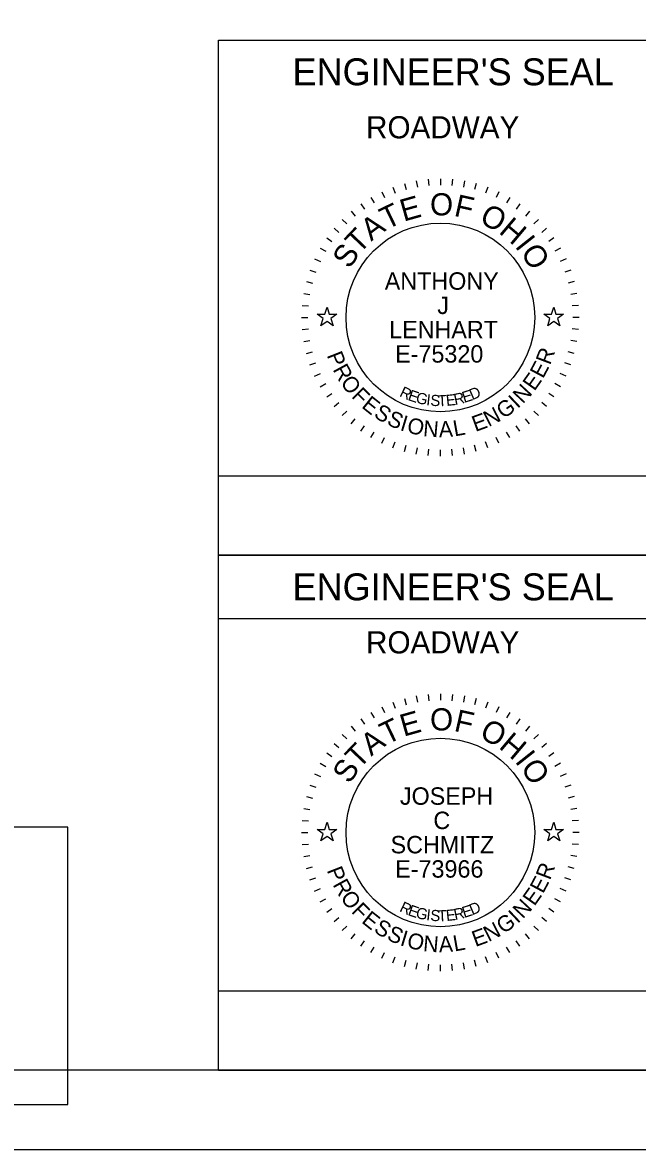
# Model space of a CAD drawing. Extents: x 208586767.6 to 208586821.4, y -134301046.9 to -134301022.9.
# Drawn here: x 208586783.14 to 208586787.02, y -134301044.94 to -134301037.83 of the extents above; entities that cross this region are included whole.
import ezdxf

# ---------------------------------------------------------------- set-up
doc = ezdxf.new("R2010")
doc.units = 0
for name, color, linetype in [('Default', 7, 'Continuous'), ('NO_PLOT', 7, 'Continuous'), ('SH_Border', 7, 'Continuous'), ('SH_Cut_Line', 7, 'Continuous'), ('SH_Data', 7, 'Continuous')]:
    doc.layers.add(name, color=color, linetype=linetype)

msp = doc.modelspace()

# ---------------------------------------------------------------- linework, layer by layer
at = {"layer": 'Default'}
for points in [[(208586785.0019, -134301039.6708), (208586785.0488, -134301039.6708), (208586785.0633, -134301039.6262), (208586785.0778, -134301039.6708), (208586785.1246, -134301039.6708), (208586785.0867, -134301039.6983), (208586785.1012, -134301039.7429), (208586785.0633, -134301039.7154), (208586785.0253, -134301039.7429), (208586785.0398, -134301039.6983)], [(208586786.4319, -134301039.6708), (208586786.4788, -134301039.6708), (208586786.4933, -134301039.6262), (208586786.5078, -134301039.6708), (208586786.5546, -134301039.6708), (208586786.5167, -134301039.6983), (208586786.5312, -134301039.7429), (208586786.4933, -134301039.7154), (208586786.4553, -134301039.7429), (208586786.4698, -134301039.6983)], [(208586785.0019, -134301042.9208), (208586785.0488, -134301042.9208), (208586785.0633, -134301042.8762), (208586785.0778, -134301042.9208), (208586785.1246, -134301042.9208), (208586785.0867, -134301042.9483), (208586785.1012, -134301042.9929), (208586785.0633, -134301042.9654), (208586785.0253, -134301042.9929), (208586785.0398, -134301042.9483)], [(208586786.4319, -134301042.9208), (208586786.4788, -134301042.9208), (208586786.4933, -134301042.8762), (208586786.5078, -134301042.9208), (208586786.5546, -134301042.9208), (208586786.5167, -134301042.9483), (208586786.5312, -134301042.9929), (208586786.4933, -134301042.9654), (208586786.4553, -134301042.9929), (208586786.4698, -134301042.9483)]]:
    msp.add_lwpolyline(points, close=True, dxfattribs=at)
at = {"layer": 'NO_PLOT'}
msp.add_lwpolyline([(208586777.4283, -134301044.6568), (208586783.4283, -134301044.6568), (208586783.4283, -134301042.9068), (208586777.4283, -134301042.9068)], close=True, dxfattribs=at)
at = {"layer": 'SH_Border'}
msp.add_lwpolyline([(208586777.4283, -134301023.4407), (208586809.4283, -134301023.4407), (208586809.4283, -134301044.4407), (208586777.4283, -134301044.4407)], close=True, dxfattribs=at)
at = {"layer": 'SH_Cut_Line'}
msp.add_lwpolyline([(208586775.9283, -134301044.9407), (208586809.9283, -134301044.9407), (208586809.9283, -134301022.9407), (208586775.9283, -134301022.9407)], close=True, dxfattribs=at)
at = {"layer": 'SH_Data'}
for p, q in [((208586784.3783, -134301041.1907), (208586784.3783, -134301037.9407)), ((208586784.3783, -134301037.9407), (208586787.1783, -134301037.9407)), ((208586785.5518, -134301038.8455), (208586785.5621, -134301038.8842)), ((208586785.6263, -134301038.829), (208586785.6333, -134301038.8684)), ((208586785.702, -134301038.819), (208586785.7055, -134301038.8589)), ((208586785.7783, -134301038.8157), (208586785.7783, -134301038.8557)), ((208586785.8545, -134301038.819), (208586785.851, -134301038.8589)), ((208586785.9302, -134301038.829), (208586785.9233, -134301038.8684)), ((208586786.0047, -134301038.8455), (208586785.9944, -134301038.8842)), ((208586785.4085, -134301038.8977), (208586785.4254, -134301038.934)), ((208586785.479, -134301038.8685), (208586785.4927, -134301038.9061)), ((208586786.0775, -134301038.8685), (208586786.0638, -134301038.9061)), ((208586786.1481, -134301038.8977), (208586786.1311, -134301038.934)), ((208586785.2764, -134301038.974), (208586785.2993, -134301039.0067)), ((208586785.3408, -134301038.9329), (208586785.3608, -134301038.9676)), ((208586786.2158, -134301038.9329), (208586786.1958, -134301038.9676)), ((208586786.2801, -134301038.974), (208586786.2572, -134301039.0067)), ((208586785.2158, -134301039.0204), (208586785.2415, -134301039.0511)), ((208586786.3407, -134301039.0204), (208586786.315, -134301039.0511)), ((208586785.108, -134301039.1283), (208586785.1386, -134301039.154)), ((208586785.1595, -134301039.072), (208586785.1878, -134301039.1003)), ((208586786.397, -134301039.072), (208586786.3687, -134301039.1003)), ((208586786.4486, -134301039.1283), (208586786.4179, -134301039.154)), ((208586785.0615, -134301039.1888), (208586785.0943, -134301039.2118)), ((208586786.495, -134301039.1888), (208586786.4623, -134301039.2118)), ((208586785.0205, -134301039.2532), (208586785.0551, -134301039.2732)), ((208586786.536, -134301039.2532), (208586786.5014, -134301039.2732)), ((208586784.9852, -134301039.3209), (208586785.0215, -134301039.3378)), ((208586786.5713, -134301039.3209), (208586786.535, -134301039.3378)), ((208586784.956, -134301039.3915), (208586784.9936, -134301039.4051)), ((208586786.6005, -134301039.3915), (208586786.5629, -134301039.4051)), ((208586784.9331, -134301039.4643), (208586784.9717, -134301039.4746)), ((208586786.6234, -134301039.4643), (208586786.5848, -134301039.4746)), ((208586784.9166, -134301039.5388), (208586784.9559, -134301039.5457)), ((208586786.64, -134301039.5388), (208586786.6006, -134301039.5457)), ((208586784.9066, -134301039.6145), (208586784.9464, -134301039.6179)), ((208586786.6499, -134301039.6145), (208586786.6101, -134301039.6179)), ((208586784.9033, -134301039.6907), (208586784.9433, -134301039.6907)), ((208586786.6533, -134301039.6907), (208586786.6133, -134301039.6907)), ((208586784.9066, -134301039.767), (208586784.9464, -134301039.7635)), ((208586786.6499, -134301039.767), (208586786.6101, -134301039.7635)), ((208586784.9166, -134301039.8427), (208586784.9559, -134301039.8357)), ((208586786.64, -134301039.8427), (208586786.6006, -134301039.8357)), ((208586784.9331, -134301039.9172), (208586784.9717, -134301039.9068)), ((208586786.6234, -134301039.9172), (208586786.5848, -134301039.9068)), ((208586784.956, -134301039.99), (208586784.9936, -134301039.9763)), ((208586786.6005, -134301039.99), (208586786.5629, -134301039.9763)), ((208586784.9852, -134301040.0605), (208586785.0215, -134301040.0436)), ((208586786.5713, -134301040.0605), (208586786.535, -134301040.0436)), ((208586785.0205, -134301040.1282), (208586785.0551, -134301040.1082)), ((208586786.536, -134301040.1282), (208586786.5014, -134301040.1082)), ((208586785.0615, -134301040.1926), (208586785.0943, -134301040.1697)), ((208586786.495, -134301040.1926), (208586786.4623, -134301040.1697)), ((208586785.108, -134301040.2532), (208586785.1386, -134301040.2274)), ((208586786.4486, -134301040.2532), (208586786.4179, -134301040.2274)), ((208586785.1595, -134301040.3094), (208586785.1878, -134301040.2812)), ((208586785.2158, -134301040.361), (208586785.2415, -134301040.3304)), ((208586786.3407, -134301040.361), (208586786.315, -134301040.3304)), ((208586786.397, -134301040.3094), (208586786.3687, -134301040.2812)), ((208586785.2764, -134301040.4075), (208586785.2993, -134301040.3747)), ((208586785.3408, -134301040.4485), (208586785.3608, -134301040.4139)), ((208586786.2158, -134301040.4485), (208586786.1958, -134301040.4139)), ((208586786.2801, -134301040.4075), (208586786.2572, -134301040.3747)), ((208586785.4085, -134301040.4837), (208586785.4254, -134301040.4475)), ((208586785.479, -134301040.513), (208586785.4927, -134301040.4754)), ((208586786.0775, -134301040.513), (208586786.0638, -134301040.4754)), ((208586786.1481, -134301040.4837), (208586786.1311, -134301040.4475)), ((208586785.5518, -134301040.5359), (208586785.5621, -134301040.4973)), ((208586785.6263, -134301040.5524), (208586785.6333, -134301040.513)), ((208586785.702, -134301040.5624), (208586785.7055, -134301040.5225)), ((208586785.7783, -134301040.5657), (208586785.7783, -134301040.5257)), ((208586785.8545, -134301040.5624), (208586785.851, -134301040.5225)), ((208586785.9302, -134301040.5524), (208586785.9233, -134301040.513)), ((208586786.0047, -134301040.5359), (208586785.9944, -134301040.4973)), ((208586784.3783, -134301044.4407), (208586784.3783, -134301041.1907)), ((208586784.3783, -134301041.1907), (208586787.1783, -134301041.1907)), ((208586784.3783, -134301041.1907), (208586787.1783, -134301041.1907)), ((208586784.3783, -134301044.4407), (208586784.3783, -134301041.1907)), ((208586784.3783, -134301041.1907), (208586787.1783, -134301041.1907)), ((208586784.3783, -134301041.5907), (208586787.1783, -134301041.5907)), ((208586785.479, -134301042.1185), (208586785.4927, -134301042.1561)), ((208586785.5518, -134301042.0955), (208586785.5621, -134301042.1342)), ((208586785.6263, -134301042.079), (208586785.6333, -134301042.1184)), ((208586785.702, -134301042.069), (208586785.7055, -134301042.1089)), ((208586785.7783, -134301042.0657), (208586785.7783, -134301042.1057)), ((208586785.8545, -134301042.069), (208586785.851, -134301042.1089)), ((208586785.9302, -134301042.079), (208586785.9233, -134301042.1184)), ((208586786.0047, -134301042.0955), (208586785.9944, -134301042.1342)), ((208586786.0775, -134301042.1185), (208586786.0638, -134301042.1561)), ((208586785.3408, -134301042.1829), (208586785.3608, -134301042.2176)), ((208586785.4085, -134301042.1477), (208586785.4254, -134301042.184)), ((208586786.1481, -134301042.1477), (208586786.1311, -134301042.184)), ((208586786.2158, -134301042.1829), (208586786.1958, -134301042.2176)), ((208586785.2764, -134301042.224), (208586785.2993, -134301042.2567)), ((208586786.2801, -134301042.224), (208586786.2572, -134301042.2567)), ((208586785.1595, -134301042.322), (208586785.1878, -134301042.3503)), ((208586785.2158, -134301042.2704), (208586785.2415, -134301042.3011)), ((208586786.3407, -134301042.2704), (208586786.315, -134301042.3011)), ((208586786.397, -134301042.322), (208586786.3687, -134301042.3503)), ((208586785.108, -134301042.3783), (208586785.1386, -134301042.404)), ((208586786.4486, -134301042.3783), (208586786.4179, -134301042.404)), ((208586785.0615, -134301042.4388), (208586785.0943, -134301042.4618)), ((208586786.495, -134301042.4388), (208586786.4623, -134301042.4618)), ((208586785.0205, -134301042.5032), (208586785.0551, -134301042.5232)), ((208586786.536, -134301042.5032), (208586786.5014, -134301042.5232)), ((208586784.9852, -134301042.5709), (208586785.0215, -134301042.5878)), ((208586786.5713, -134301042.5709), (208586786.535, -134301042.5878)), ((208586784.956, -134301042.6415), (208586784.9936, -134301042.6551)), ((208586786.6005, -134301042.6415), (208586786.5629, -134301042.6551)), ((208586784.9331, -134301042.7143), (208586784.9717, -134301042.7246)), ((208586786.6234, -134301042.7143), (208586786.5848, -134301042.7246)), ((208586784.9166, -134301042.7888), (208586784.9559, -134301042.7957)), ((208586786.64, -134301042.7888), (208586786.6006, -134301042.7957)), ((208586784.9066, -134301042.8645), (208586784.9464, -134301042.8679)), ((208586786.6499, -134301042.8645), (208586786.6101, -134301042.8679)), ((208586784.9033, -134301042.9407), (208586784.9433, -134301042.9407)), ((208586786.6533, -134301042.9407), (208586786.6133, -134301042.9407)), ((208586784.9066, -134301043.017), (208586784.9464, -134301043.0135)), ((208586786.6499, -134301043.017), (208586786.6101, -134301043.0135)), ((208586784.9166, -134301043.0927), (208586784.9559, -134301043.0857)), ((208586786.64, -134301043.0927), (208586786.6006, -134301043.0857)), ((208586784.9331, -134301043.1672), (208586784.9717, -134301043.1568)), ((208586786.6234, -134301043.1672), (208586786.5848, -134301043.1568)), ((208586784.956, -134301043.24), (208586784.9936, -134301043.2263)), ((208586786.6005, -134301043.24), (208586786.5629, -134301043.2263)), ((208586784.9852, -134301043.3105), (208586785.0215, -134301043.2936)), ((208586786.5713, -134301043.3105), (208586786.535, -134301043.2936)), ((208586785.0205, -134301043.3782), (208586785.0551, -134301043.3582)), ((208586786.536, -134301043.3782), (208586786.5014, -134301043.3582)), ((208586785.0615, -134301043.4426), (208586785.0943, -134301043.4197)), ((208586786.495, -134301043.4426), (208586786.4623, -134301043.4197)), ((208586785.108, -134301043.5032), (208586785.1386, -134301043.4774)), ((208586785.1595, -134301043.5594), (208586785.1878, -134301043.5312)), ((208586786.397, -134301043.5594), (208586786.3687, -134301043.5312)), ((208586786.4486, -134301043.5032), (208586786.4179, -134301043.4774)), ((208586785.2158, -134301043.611), (208586785.2415, -134301043.5804)), ((208586786.3407, -134301043.611), (208586786.315, -134301043.5804)), ((208586785.2764, -134301043.6575), (208586785.2993, -134301043.6247)), ((208586785.3408, -134301043.6985), (208586785.3608, -134301043.6639)), ((208586786.2158, -134301043.6985), (208586786.1958, -134301043.6639)), ((208586786.2801, -134301043.6575), (208586786.2572, -134301043.6247)), ((208586785.4085, -134301043.7337), (208586785.4254, -134301043.6975)), ((208586785.479, -134301043.763), (208586785.4927, -134301043.7254)), ((208586785.5518, -134301043.7859), (208586785.5621, -134301043.7473)), ((208586786.0047, -134301043.7859), (208586785.9944, -134301043.7473)), ((208586786.0775, -134301043.763), (208586786.0638, -134301043.7254)), ((208586786.1481, -134301043.7337), (208586786.1311, -134301043.6975)), ((208586785.6263, -134301043.8024), (208586785.6333, -134301043.763)), ((208586785.702, -134301043.8124), (208586785.7055, -134301043.7725)), ((208586785.7783, -134301043.8157), (208586785.7783, -134301043.7757)), ((208586785.8545, -134301043.8124), (208586785.851, -134301043.7725)), ((208586785.9302, -134301043.8024), (208586785.9233, -134301043.763)), ((208586784.3783, -134301044.4407), (208586787.1783, -134301044.4407))]:
    msp.add_line(p, q, dxfattribs=at)
for points in [[(208586784.3783, -134301041.1907), (208586784.3783, -134301040.6907), (208586787.1783, -134301040.6907), (208586787.1783, -134301041.1907)], [(208586784.3783, -134301044.4407), (208586784.3783, -134301043.9407), (208586787.1783, -134301043.9407), (208586787.1783, -134301044.4407)]]:
    msp.add_lwpolyline(points, close=True, dxfattribs=at)
for centre in [(208586785.7783, -134301039.6907), (208586785.7783, -134301042.9407)]:
    msp.add_circle(centre, 0.595, dxfattribs=at)

# ---------------------------------------------------------------- texts
for s, height, p in [("ENGINEER'S SEAL", 0.17, (208586784.8458, -134301038.2257)), ('ROADWAY', 0.14, (208586785.3094, -134301038.5607)), ('ANTHONY', 0.11, (208586785.4275, -134301039.5158)), ('J', 0.11, (208586785.7591, -134301039.6691)), ('LENHART', 0.11, (208586785.4553, -134301039.8224)), ('E-75320', 0.11, (208586785.4932, -134301039.9756)), ("ENGINEER'S SEAL", 0.17, (208586784.8458, -134301041.4757)), ('ROADWAY', 0.14, (208586785.3094, -134301041.8107)), ('JOSEPH', 0.11, (208586785.5232, -134301042.7658)), ('C', 0.11, (208586785.7344, -134301042.9191)), ('SCHMITZ', 0.11, (208586785.4644, -134301043.0724)), ('E-73966', 0.11, (208586785.4937, -134301043.2256))]:
    msp.add_text(s, height=height, dxfattribs=at).set_placement(p)
for s, height, rotation, p in [('E', 0.14, 15.75706, (208586785.5467, -134301039.0869)), ('O', 0.14, 359.78119, (208586785.713, -134301039.0465)), ('F', 0.14, 347.43619, (208586785.8593, -134301039.049)), ('T', 0.14, 25.71674, (208586785.4399, -134301039.1389)), ('O', 0.14, 332.25863, (208586786.0181, -134301039.0892)), ('A', 0.14, 36.47472, (208586785.3417, -134301039.2126)), ('H', 0.14, 319.91363, (208586786.1414, -134301039.1546)), ('T', 0.14, 46.4344, (208586785.2666, -134301039.2943)), ('I', 0.14, 308.36695, (208586786.2447, -134301039.2424)), ('S', 0.14, 57.19238, (208586785.2064, -134301039.3893)), ('O', 0.14, 303.14906, (208586786.2804, -134301039.2819)), ('P', 0.1, 291.49398, (208586785.0605, -134301039.9287)), ('R', 0.1, 69.23216, (208586786.4702, -134301039.9953)), ('R', 0.1, 298.73106, (208586785.0972, -134301040.019)), ('E', 0.1, 61.99508, (208586786.4259, -134301040.0809)), ('E', 0.1, 54.75801, (208586786.3716, -134301040.1594)), ('O', 0.1, 306.46664, (208586785.1437, -134301040.1024)), ('F', 0.1, 314.7068, (208586785.2126, -134301040.1924)), ('R', 0.07, 334.48695, (208586785.5158, -134301040.1857)), ('D', 0.07, 23.30524, (208586785.9793, -134301040.2137)), ('N', 0.1, 47.02243, (208586786.2985, -134301040.2399)), ('E', 0.1, 321.43929, (208586785.2761, -134301040.2559)), ('E', 0.07, 341.03996, (208586785.5689, -134301040.2107)), ('G', 0.07, 347.47515, (208586785.6197, -134301040.2289)), ('I', 0.07, 353.78581, (208586785.6873, -134301040.2439)), ('S', 0.07, 356.89262, (208586785.714, -134301040.2478)), ('T', 0.07, 3.00609, (208586785.764, -134301040.252)), ('E', 0.07, 6.01169, (208586785.8172, -134301040.2495)), ('R', 0.07, 11.91844, (208586785.8708, -134301040.2433)), ('E', 0.07, 17.68363, (208586785.9281, -134301040.2305)), ('I', 0.1, 43.28703, (208586786.2651, -134301040.2693)), ('S', 0.1, 328.67637, (208586785.3526, -134301040.3155)), ('N', 0.1, 27.31129, (208586786.0827, -134301040.3832)), ('G', 0.1, 35.04687, (208586786.1763, -134301040.3337)), ('S', 0.1, 335.91345, (208586785.4347, -134301040.3641)), ('I', 0.1, 343.15053, (208586785.5189, -134301040.401)), ('O', 0.1, 346.88592, (208586785.5621, -134301040.4156)), ('N', 0.1, 355.12608, (208586785.6671, -134301040.439)), ('A', 0.1, 2.86166, (208586785.7705, -134301040.447)), ('L', 0.1, 10.09874, (208586785.8677, -134301040.4417)), ('E', 0.1, 20.07421, (208586785.9995, -134301040.4137)), ('E', 0.14, 15.75706, (208586785.5467, -134301042.3369)), ('O', 0.14, 359.78119, (208586785.713, -134301042.2965)), ('F', 0.14, 347.43619, (208586785.8593, -134301042.299)), ('T', 0.14, 25.71674, (208586785.4399, -134301042.3889)), ('O', 0.14, 332.25863, (208586786.0181, -134301042.3392)), ('A', 0.14, 36.47472, (208586785.3417, -134301042.4626)), ('H', 0.14, 319.91363, (208586786.1414, -134301042.4046)), ('T', 0.14, 46.4344, (208586785.2666, -134301042.5443)), ('S', 0.14, 57.19238, (208586785.2064, -134301042.6393)), ('I', 0.14, 308.36695, (208586786.2447, -134301042.4924)), ('O', 0.14, 303.14906, (208586786.2804, -134301042.5319)), ('P', 0.1, 291.49398, (208586785.0605, -134301043.1787)), ('R', 0.1, 69.23216, (208586786.4702, -134301043.2453)), ('R', 0.1, 298.73106, (208586785.0972, -134301043.269)), ('E', 0.1, 61.99508, (208586786.4259, -134301043.3309)), ('O', 0.1, 306.46664, (208586785.1437, -134301043.3524)), ('E', 0.1, 54.75801, (208586786.3716, -134301043.4094)), ('F', 0.1, 314.7068, (208586785.2126, -134301043.4424)), ('R', 0.07, 334.48695, (208586785.5158, -134301043.4357)), ('E', 0.07, 341.03996, (208586785.5689, -134301043.4607)), ('E', 0.07, 17.68363, (208586785.9281, -134301043.4805)), ('D', 0.07, 23.30524, (208586785.9793, -134301043.4637)), ('N', 0.1, 47.02243, (208586786.2985, -134301043.4899)), ('E', 0.1, 321.43929, (208586785.2761, -134301043.5059)), ('G', 0.07, 347.47515, (208586785.6197, -134301043.4789)), ('I', 0.07, 353.78581, (208586785.6873, -134301043.4939)), ('S', 0.07, 356.89262, (208586785.714, -134301043.4978)), ('T', 0.07, 3.00609, (208586785.764, -134301043.502)), ('E', 0.07, 6.01169, (208586785.8172, -134301043.4995)), ('R', 0.07, 11.91844, (208586785.8708, -134301043.4933)), ('G', 0.1, 35.04687, (208586786.1763, -134301043.5837)), ('I', 0.1, 43.28703, (208586786.2651, -134301043.5193)), ('S', 0.1, 328.67637, (208586785.3526, -134301043.5655)), ('S', 0.1, 335.91345, (208586785.4347, -134301043.6141)), ('E', 0.1, 20.07421, (208586785.9995, -134301043.6637)), ('N', 0.1, 27.31129, (208586786.0827, -134301043.6332)), ('I', 0.1, 343.15053, (208586785.5189, -134301043.651)), ('O', 0.1, 346.88592, (208586785.5621, -134301043.6656)), ('N', 0.1, 355.12608, (208586785.6671, -134301043.689)), ('A', 0.1, 2.86166, (208586785.7705, -134301043.697)), ('L', 0.1, 10.09874, (208586785.8677, -134301043.6917))]:
    msp.add_text(s, height=height, rotation=rotation, dxfattribs=at).set_placement(p)

doc.saveas('drawing.dxf')
